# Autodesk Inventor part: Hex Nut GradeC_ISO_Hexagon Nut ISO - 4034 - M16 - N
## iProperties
Shininess: 64.0
Length Units: 11269
Angle Units: 11279
Time Units: 11290
Mass Units: 11283
Length Display Precision: 3
Angle Display Precision: 2
Compacted: True
Part Number: Hex Nut GradeC_ISO_Hexagon Nut ISO - 4034 - M16 - N
Document SubType Name: Modeling
Created: 2006-11
Material: Par défaut
Designer: profs_sti
Density: 0.0
Volumn: 0.0
Area: 0.0
PropertySet Name: Model Information
Control State: 0
Master: False
Checked Out: False
Author: profs_sti
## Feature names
1. Base1
